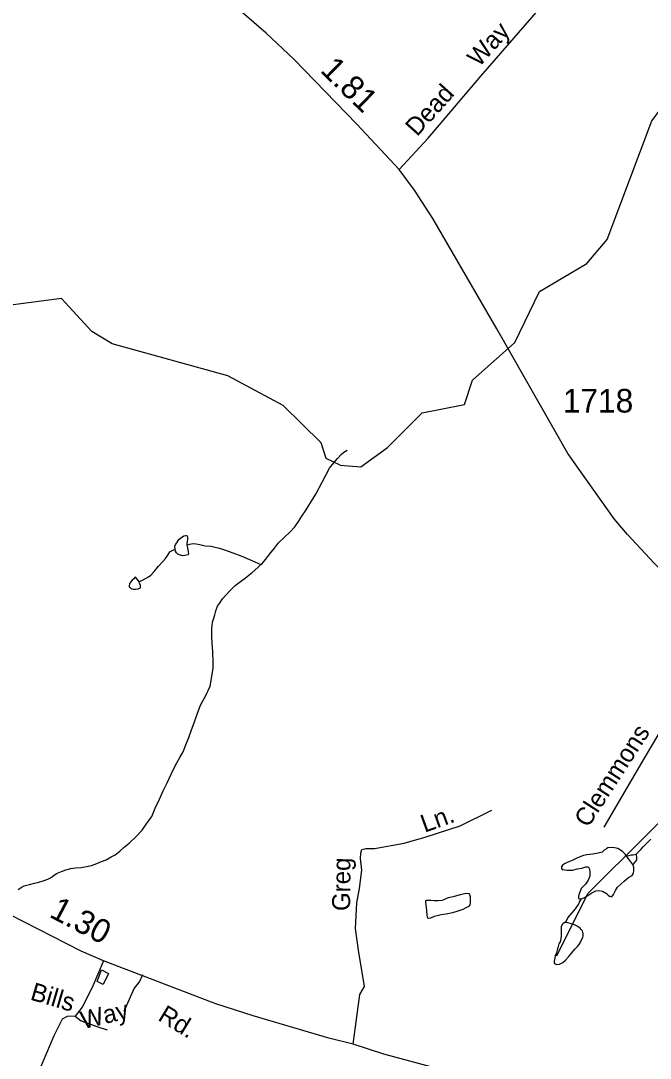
# Model space of a CAD drawing. Extents: x 2126262 to 2293712, y 749403 to 919119.
# Drawn here: x 2212194 to 2215516, y 795436 to 800917 of the extents above; entities that cross this region are included whole.
import ezdxf

# ---------------------------------------------------------------- set-up
doc = ezdxf.new("R2010")
doc.units = 0
for name, color, linetype in [('Exist Hydrographic Misc Water Feature', 7, 'Continuous'), ('Exist Road Non-System Type 51', 7, 'Continuous'), ('Exist Road Non-System Type 51 Label', 7, 'Continuous'), ('Exist Road Secondary Mileage Hundredths English Label', 7, 'Continuous'), ('Exist Road Secondary Type 51 Attributed', 7, 'Continuous'), ('Exist Road Secondary Type 51 Label', 7, 'Continuous'), ('Exist Road Secondary Type 51 Number Label', 7, 'Continuous')]:
    doc.layers.add(name, color=color, linetype=linetype)

msp = doc.modelspace()

# ---------------------------------------------------------------- linework, layer by layer
at = {"layer": 'Exist Hydrographic Misc Water Feature'}
for points in [[(2213880.4, 798569.4), (2213989.3, 798560.6), (2214130.4, 798662.7), (2214312.5, 798845.8), (2214536.4, 798890.4), (2214577.4, 799017.5), (2214801.3, 799216.3), (2214932.4, 799485.9), (2215181.5, 799634.9), (2215288.3, 799760.6), (2215525.4, 800388.8), (2215707.5, 800631.1), (2215781.5, 800806.7), (2215894.5, 801348.9), (2216043.4, 801490.2)], [(2215023.4, 795977.3), (2215187.4, 796305.3), (2215799.3, 796915.9), (2215972.4, 797283), (2216169.4, 797620.1), (2216233.4, 798028.8), (2216382.5, 798179.9), (2216523.4, 798245.9), (2216614.4, 798345.7), (2216663.4, 798456.2), (2216653.4, 798814), (2216818.4, 799007.4), (2217007.5, 799341.4), (2217073.3, 799408.9), (2217148.4, 799433.6), (2217247.4, 799549.6), (2217246.4, 799694), (2217196.3, 799793.5), (2217211.3, 799891.5), (2217444.5, 800050.8), (2217592.5, 800254.4), (2217798.4, 800630.6), (2217906.5, 800703.8), (2218039.5, 800724.1)], [(2213880.4, 798569.4), (2213805.4, 798603.7), (2213779.4, 798686.2), (2213578.4, 798884), (2213286.4, 799040.9), (2212676.4, 799210.8), (2212568.3, 799275.4), (2212408.4, 799449.3), (2211884.5, 799381.3), (2211309.5, 799376.8), (2211018.3, 799323.8), (2210686.4, 799156.7), (2210511.5, 799104.6), (2210253.5, 799119.7), (2210119.4, 799158.5), (2209985.5, 799276.2), (2209941.4, 799582.1), (2209907.4, 799700.9), (2209832.5, 799774.6), (2209656.4, 799840.5), (2209256.5, 799904.6)], [(2213461.4, 798043.7), (2213467.5, 798049.7), (2213487.4, 798071.9), (2213509.1, 798100.1), (2213532.9, 798130.2), (2213554.7, 798158.3), (2213584.4, 798186.5), (2213614.3, 798214.7), (2213640.2, 798242.9), (2213659.9, 798271), (2213677.7, 798299.1), (2213697.4, 798327.3), (2213711.3, 798351.3), (2213729.2, 798379.5), (2213750.9, 798415.6), (2213784.3, 798479.8), (2213804.2, 798516), (2213823.9, 798554), (2213845.6, 798582.2), (2213865.3, 798604.4), (2213887.5, 798626.4), (2213899.2, 798638.5), (2213917.2, 798648.6)], [(2213009.2, 798124.6), (2213007, 798140.6), (2213010.9, 798150.6), (2213017, 798158.6), (2213028.7, 798176.7), (2213038.8, 798184.8), (2213046.8, 798190.8), (2213054.8, 798194.9), (2213062.7, 798196.9), (2213066.6, 798196.9), (2213072.6, 798195), (2213074.6, 798189), (2213074.6, 798179), (2213073, 798165), (2213071, 798153), (2213071, 798147)], [(2212818.3, 797953.3), (2212824.5, 797955.4), (2212836.4, 797961.4), (2212852.2, 797969.6), (2212868.2, 797979.7), (2212880.3, 797987.8), (2212897.9, 798007.9), (2212921.7, 798036), (2212943.6, 798060.2), (2212957.4, 798076.2), (2212969.5, 798094.3), (2212981.1, 798110.4), (2212997.1, 798120.5), (2213009.2, 798124.6)], [(2213071, 798147), (2213073.2, 798133), (2213075.3, 798123), (2213077.1, 798109.1), (2213079.2, 798103.1), (2213077.5, 798095.1), (2213069.5, 798093), (2213059.5, 798091), (2213047.4, 798090.9), (2213037.3, 798092.8), (2213023.4, 798098.7), (2213015.2, 798106.6), (2213011.1, 798114.6), (2213009.2, 798124.6)], [(2213071, 798147), (2213074.8, 798149), (2213086.9, 798151.1), (2213102.9, 798155.2), (2213118.9, 798153.3), (2213138.8, 798149.5), (2213166.9, 798143.7), (2213198.9, 798141.9), (2213220.8, 798136.1), (2213243, 798130.2), (2213269.2, 798122.4), (2213313.1, 798106.7), (2213361.1, 798089), (2213429.4, 798057.5), (2213461.4, 798043.7)], [(2212180, 796327.6), (2212195.6, 796337.7), (2212211.6, 796345.7), (2212239.7, 796353.9), (2212265.7, 796360.1), (2212289.5, 796366.3), (2212311.4, 796372.4), (2212337.5, 796382.6), (2212351.4, 796388.7), (2212383.2, 796410.9), (2212409.2, 796423.1), (2212431, 796431.2), (2212458.9, 796437.4), (2212482.9, 796441.6), (2212513, 796443.8), (2212540.9, 796448), (2212566.9, 796454.2), (2212594.6, 796464.4), (2212620.7, 796474.5), (2212644.6, 796484.7), (2212670.5, 796498.9), (2212692.4, 796511), (2212716.2, 796529.2), (2212740.2, 796551.3), (2212765.8, 796571.5), (2212803.6, 796607.7), (2212835.3, 796639.9), (2212857.1, 796674), (2212880.9, 796706.2), (2212885, 796712.2), (2212902.6, 796756.4), (2212926.2, 796804.5), (2212945.9, 796848.6), (2212965.8, 796890.7), (2212989.3, 796940.9), (2213007, 796977), (2213016.8, 796997.1), (2213032.6, 797025.2), (2213050.4, 797055.2), (2213062.1, 797083.3), (2213081.8, 797129.4), (2213095.8, 797171.6), (2213109.5, 797207.6), (2213125.1, 797253.7), (2213142.7, 797301.8), (2213170.4, 797352), (2213194.2, 797402.1), (2213201.6, 797452.2), (2213209.4, 797496.2), (2213209.2, 797528.2), (2213206.9, 797582.1), (2213204.4, 797628.1), (2213202.2, 797666), (2213202, 797704.1), (2213205.7, 797740.1), (2213211.6, 797756.1), (2213217.4, 797778.1), (2213223.5, 797800.2), (2213233.1, 797824.2), (2213243, 797838.3), (2213259, 797862.4), (2213276.6, 797882.5), (2213296.7, 797904.6), (2213326.4, 797932.8), (2213354.1, 797955), (2213380.2, 797973.2), (2213415.8, 798001.4), (2213445.6, 798027.6), (2213461.4, 798043.7)], [(2212818.3, 797953.3), (2212810.3, 797965.3), (2212802.1, 797975.3), (2212798.2, 797977.2), (2212790.4, 797969.1), (2212782.4, 797961.1), (2212774.4, 797953.1), (2212770.3, 797945), (2212768.5, 797941), (2212766.7, 797933), (2212766.7, 797927), (2212770.8, 797923), (2212776.7, 797917.1), (2212780.6, 797915.1), (2212786.7, 797913.1), (2212794.7, 797913.2), (2212800.7, 797913.2), (2212812.6, 797915.3), (2212822.6, 797919.4), (2212826.7, 797921.4), (2212826.3, 797933.4), (2212820.4, 797945.4), (2212818.3, 797953.3)], [(2215441.4, 796512), (2215443.4, 796515.9), (2215455.1, 796526), (2215467.2, 796538.1), (2215478.9, 796552.2), (2215500.8, 796574.3), (2215518.7, 796592.4)], [(2215390.9, 796503.7), (2215383.3, 796513.5), (2215369.2, 796527.4), (2215345.2, 796543.3), (2215327.1, 796547.1), (2215313.2, 796549), (2215293.1, 796546.9), (2215285.1, 796542.8), (2215273.2, 796534.8), (2215263.4, 796524.7), (2215241.4, 796518.6), (2215213.3, 796514.4), (2215181.3, 796510.2), (2215163.3, 796506), (2215131.7, 796493.8), (2215103.6, 796479.7), (2215077.6, 796469.5), (2215063.9, 796463.4), (2215053.8, 796455.3), (2215047.9, 796447.3), (2215047.9, 796443.3), (2215047.9, 796437.3), (2215052, 796433.3), (2215065.9, 796431.4), (2215078, 796429.5), (2215105.9, 796429.6), (2215131.9, 796435.8), (2215155.9, 796440), (2215175.8, 796446.1), (2215179.9, 796446.1), (2215185.9, 796446.2), (2215190, 796444.3), (2215195.9, 796434.2), (2215198.2, 796420.3), (2215198.2, 796408.3), (2215198.2, 796398.3), (2215194.1, 796388.3), (2215188.3, 796376.3), (2215174.4, 796356.1), (2215164.7, 796344.1), (2215152.6, 796332), (2215148.7, 796322), (2215142.8, 796309.9), (2215136.9, 796291.9), (2215136.9, 796283.9), (2215136.9, 796279.9), (2215143.2, 796277.9), (2215153, 796278)], [(2215441.4, 796512), (2215425.4, 796507.9), (2215415.3, 796507.7), (2215403.4, 796505.7), (2215390.9, 796503.7)], [(2215423.7, 796459.8), (2215403.4, 796487.7), (2215390.9, 796503.7)], [(2215441.4, 796512), (2215441.4, 796508), (2215443.4, 796498), (2215443.4, 796494), (2215443.4, 796490), (2215443.4, 796484), (2215433.6, 796469.9), (2215423.7, 796459.8)], [(2215153, 796278), (2215168.8, 796284.1), (2215192.8, 796298.3), (2215208.8, 796310.4), (2215228.7, 796320.6), (2215244.7, 796322.6), (2215264.6, 796318.8), (2215284.9, 796306.9), (2215294.9, 796297), (2215300.9, 796291.1), (2215313, 796289.1), (2215322.8, 796301.2), (2215332.7, 796321.3), (2215342.7, 796339.3), (2215362.4, 796357.4), (2215378.4, 796371.6), (2215392.1, 796383.6), (2215402.2, 796389.7), (2215420.2, 796401.8), (2215426, 796409.9), (2215427.8, 796415.9), (2215429.9, 796425.9), (2215429.7, 796445.9), (2215423.7, 796459.8)], [(2214461.2, 796287.3), (2214483.1, 796291.4), (2214515.1, 796301.6), (2214535.2, 796305.8), (2214551.2, 796307.9), (2214559.2, 796305.9), (2214563.1, 796299.9), (2214565.2, 796290), (2214565.4, 796274), (2214565.4, 796260), (2214563.3, 796246), (2214559.4, 796239.9), (2214555.7, 796236), (2214543.6, 796229.9), (2214527.6, 796221.8), (2214501.6, 796213.5), (2214471.9, 796203.3), (2214439.9, 796197.1), (2214412, 796192.9), (2214391.9, 796188.8), (2214375.9, 796184.7), (2214355.8, 796176.5), (2214348.2, 796174.5), (2214342.1, 796176.5), (2214339.8, 796190.4), (2214337.6, 796216.4), (2214333.7, 796248.4), (2214331.4, 796260.4), (2214331.4, 796268.3), (2214337.4, 796270.5), (2214357.4, 796270.6), (2214377.3, 796268.7), (2214397.4, 796268.8), (2214419.4, 796271), (2214435.4, 796277.1), (2214451.2, 796285.2), (2214461.2, 796287.3)], [(2215069.8, 796153.5), (2215073.9, 796161.5), (2215081.7, 796177.6), (2215091.7, 796189.6), (2215103.6, 796203.7), (2215121.5, 796225.8), (2215137.1, 796247.9), (2215143.2, 796260), (2215153, 796278)], [(2215069.8, 796153.5), (2215065.9, 796153.5), (2215055.9, 796147.4), (2215052, 796141.4), (2215046.2, 796129.4), (2215046.2, 796111.4), (2215046.4, 796079.4), (2215040.7, 796051.3), (2215034.7, 796039.3), (2215029, 796019.3), (2215024.9, 796007.3), (2215021.2, 795993.3), (2215015, 795977.2), (2215013.2, 795965.2), (2215009.3, 795949.2), (2215009.3, 795939.2), (2215013.4, 795935.2), (2215023.5, 795931.2), (2215037.4, 795933.4), (2215055.4, 795941.5), (2215069.4, 795953.5), (2215085.2, 795971.7), (2215102.8, 795991.8), (2215118.8, 796011.9), (2215132.5, 796026), (2215140.7, 796036.1), (2215146.7, 796046.1), (2215150.6, 796054.1), (2215160.4, 796074.2), (2215162.5, 796084.2), (2215162.5, 796092.2), (2215160.2, 796102.2), (2215158.2, 796108.2), (2215152.2, 796116), (2215146.1, 796122), (2215130.1, 796133.9), (2215115.9, 796139.8), (2215094, 796147.7), (2215081.9, 796151.6), (2215069.8, 796153.5)], [(2212656.7, 795883), (2212629.1, 795824.8), (2212596.9, 795840.6), (2212620.7, 795902.7), (2212656.7, 795883)]]:
    msp.add_lwpolyline(points, dxfattribs=at)
at = {"layer": 'Exist Road Non-System Type 51'}
for points in [[(2214190.5, 800131.6), (2214344.1, 800296.8), (2214622.9, 800625.1), (2214996.8, 801057.5)], [(2215962.8, 797610.7), (2215765.9, 797428.3), (2215629.2, 797263.5), (2215484.1, 797020.5), (2215272.1, 796655.8)], [(2213987.8, 796491.3), (2213988.1, 796519), (2213994.7, 796538.7), (2214014.5, 796543.1), (2214060.7, 796543.1), (2214216.7, 796571.7), (2214333.2, 796604.7), (2214513.4, 796664.1), (2214680.5, 796745.5)], [(2213948.1, 795509.3), (2213966.9, 795654.6), (2213982.9, 795772.6), (2214008, 795814.5), (2213977.3, 796007.3), (2213960.6, 796120.4), (2213966.9, 796256.6), (2213982.2, 796332), (2213993.4, 796429.8), (2213987.8, 796491.3)], [(2212631.4, 795949.9), (2212570.6, 795809.7), (2212517.6, 795706.3), (2212481.6, 795657.1)], [(2212836.5, 795875.9), (2212821.1, 795840.4), (2212793.2, 795805.5), (2212737.4, 795682.5)], [(2212481.6, 795657.1), (2212438, 795655.3), (2212412.9, 795642.7), (2212368.2, 795554.7), (2212309.6, 795416.5), (2212258, 795296.3)], [(2212481.6, 795657.1), (2212512.3, 795633.3), (2212601, 795601.2), (2212649.5, 795585.5)]]:
    msp.add_lwpolyline(points, dxfattribs=at)
at = {"layer": 'Exist Road Secondary Type 51 Attributed'}
for points in [[(2216710.6, 796551.6), (2216527.1, 796876.2), (2216282.7, 797281), (2215537.8, 798051.4), (2215396.9, 798202.2), (2215325.7, 798286), (2215082.2, 798630.3), (2214706.2, 799288.8), (2214369.2, 799871.9), (2214271.5, 800021.3), (2214190.5, 800131.6), (2213968, 800371.2), (2213635.2, 800714), (2213490, 800850.9), (2213319.8, 800997.5)], [(2215479.3, 795107.4), (2214934, 795234.8), (2214110, 795457.6), (2213948.1, 795509.3), (2213819.7, 795541.4), (2213419.9, 795659.4), (2213223.1, 795723.7), (2212631.4, 795949.9), (2212513.5, 796000.9), (2212135.3, 796195.1), (2211375.4, 796627.4), (2211195.4, 796746.1), (2211036.3, 796841.1), (2210076.1, 797480.8), (2209962.4, 797552.7), (2209568.1, 797792.3), (2209389.5, 797892.8), (2209286.9, 797956.2)]]:
    msp.add_lwpolyline(points, dxfattribs=at)

# ---------------------------------------------------------------- texts
at = {"layer": 'Exist Road Non-System Type 51 Label'}
for s, rotation, p in [('Way', 48.2492, (2214612.3, 800667.8)), ('Dead', 48.2492, (2214285.7, 800301.9)), ('Clemmons', 57.1209, (2215188.6, 796649.3)), ('Ln.', 19.9448, (2214325.6, 796626.4)), ('Greg', 89.4887, (2213932.1, 796213.2)), ('Bills', 343.5618, (2212238.9, 795746.5)), ('Way', 13.7542, (2212523, 795588.2))]:
    msp.add_text(s, height=95, rotation=rotation, dxfattribs=at).set_placement(p)
at = {"layer": 'Exist Road Secondary Mileage Hundredths English Label'}
for s, rotation, p in [('1.81', 315.7931, (2213769.3, 800650.2)), ('1.30', 332.2533, (2212339, 796185.1))]:
    msp.add_text(s, height=125, rotation=rotation, dxfattribs=at).set_placement(p)
at = {"layer": 'Exist Road Secondary Type 51 Label'}
msp.add_text('Rd.', height=95, rotation=328.685, dxfattribs=at).set_placement((2212912.3, 795639.9))
at = {"layer": 'Exist Road Secondary Type 51 Number Label'}
msp.add_text('1718', height=125, dxfattribs=at).set_placement((2215054.9, 798847))

doc.saveas('drawing.dxf')
